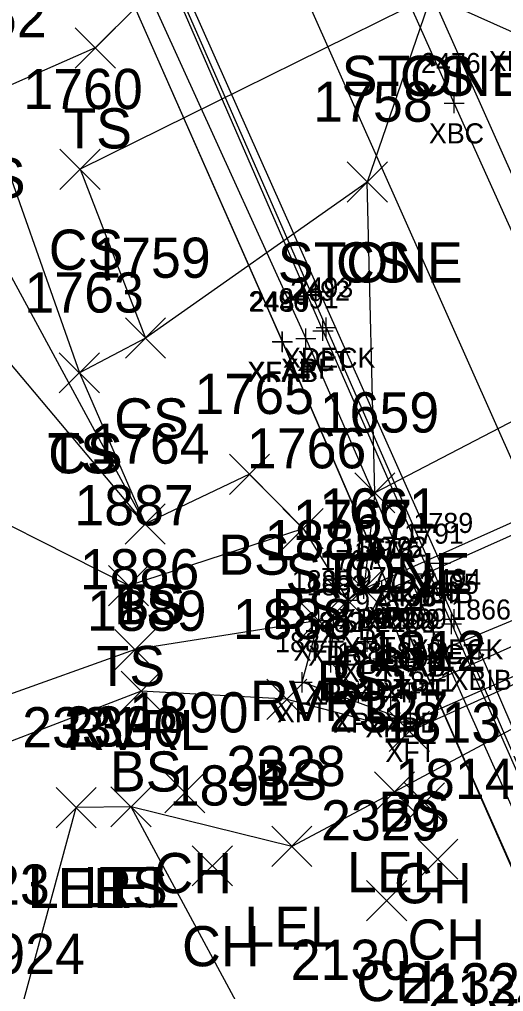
# Model space of a CAD drawing. Extents: x 1504228 to 1506103, y 437717 to 440106.
# Drawn here: x 1505177.43 to 1505201.55, y 438165.51 to 438213.89 of the extents above; entities that cross this region are included whole.
import ezdxf

# ---------------------------------------------------------------- set-up
doc = ezdxf.new("R2010")
doc.units = 0
for name, color, linetype in [('B_A', 7, 'Continuous'), ('B_I', 7, 'Continuous'), ('B_TIC', 7, 'Continuous'), ('BB', 7, 'Continuous'), ('BDC', 7, 'Continuous'), ('BELB', 7, 'Continuous'), ('BF', 7, 'Continuous'), ('BFT', 7, 'Continuous'), ('BR', 7, 'Continuous'), ('BSUBM', 7, 'Continuous'), ('L_A', 7, 'Continuous'), ('L_I', 7, 'Continuous'), ('L_TIC', 7, 'Continuous'), ('LARO', 7, 'Continuous'), ('LASF', 7, 'Continuous'), ('LAWE', 7, 'Continuous'), ('LELB', 7, 'Continuous')]:
    doc.layers.add(name, color=color, linetype=linetype)

msp = doc.modelspace()

# ---------------------------------------------------------------- linework, layer by layer
at = {"layer": 'B_TIC'}
for p, q in [((1505199.096, 438209.718), (1505199.172, 438209.718)), ((1505192.559, 438198.391), (1505192.634, 438198.391)), ((1505192.72, 438198.549), (1505192.795, 438198.549)), ((1505190.521, 438197.862), (1505190.596, 438197.862)), ((1505190.544, 438197.836), (1505190.62, 438197.836)), ((1505191.703, 438198.009), (1505191.779, 438198.009)), ((1505198.413, 438186.83), (1505198.489, 438186.83)), ((1505197.658, 438186.296), (1505197.734, 438186.296)), ((1505196.095, 438185.646), (1505196.171, 438185.646)), ((1505194.585, 438185.548), (1505194.661, 438185.548)), ((1505195.488, 438185.416), (1505195.563, 438185.416)), ((1505195.886, 438185.587), (1505195.962, 438185.587)), ((1505193.792, 438184.98), (1505193.867, 438184.98)), ((1505192.345, 438183.974), (1505192.421, 438183.974)), ((1505193.085, 438183.722), (1505193.16, 438183.722)), ((1505193.085, 438183.722), (1505193.16, 438183.722)), ((1505194.849, 438184.144), (1505194.925, 438184.144)), ((1505198.964, 438183.8), (1505199.039, 438183.8)), ((1505199.093, 438184.038), (1505199.168, 438184.038)), ((1505196.854, 438183.23), (1505196.929, 438183.23)), ((1505198.06, 438183.407), (1505198.135, 438183.407)), ((1505194.765, 438182.92), (1505194.84, 438182.92)), ((1505196.881, 438183.176), (1505196.957, 438183.176)), ((1505200.343, 438182.519), (1505200.419, 438182.519)), ((1505192.955, 438181.893), (1505193.03, 438181.893)), ((1505195.545, 438182.063), (1505195.621, 438182.063)), ((1505196.815, 438181.895), (1505196.89, 438181.895)), ((1505197.342, 438182.037), (1505197.418, 438182.037)), ((1505197.379, 438182.065), (1505197.455, 438182.065)), ((1505191.52, 438180.897), (1505191.595, 438180.897)), ((1505194.333, 438180.389), (1505194.409, 438180.389)), ((1505196.874, 438180.394), (1505196.949, 438180.394)), ((1505195.932, 438180.154), (1505196.008, 438180.154)), ((1505196.924, 438178.938), (1505196.999, 438178.938))]:
    msp.add_line(p, q, dxfattribs=at)
for points in [[(1505199.093, 438209.218), (1505199.093, 438210.218)], [(1505198.593, 438209.718), (1505199.593, 438209.718)], [(1505192.555, 438197.891), (1505192.555, 438198.891)], [(1505192.716, 438198.049), (1505192.716, 438199.049)], [(1505190.518, 438197.362), (1505190.518, 438198.362)], [(1505190.541, 438197.336), (1505190.541, 438198.336)], [(1505191.7, 438197.509), (1505191.7, 438198.509)], [(1505192.055, 438198.391), (1505193.055, 438198.391)], [(1505192.216, 438198.549), (1505193.216, 438198.549)], [(1505190.018, 438197.862), (1505191.018, 438197.862)], [(1505190.041, 438197.836), (1505191.041, 438197.836)], [(1505191.2, 438198.009), (1505192.2, 438198.009)], [(1505198.41, 438186.33), (1505198.41, 438187.33)], [(1505197.655, 438185.796), (1505197.655, 438186.796)], [(1505197.91, 438186.83), (1505198.91, 438186.83)], [(1505196.092, 438185.146), (1505196.092, 438186.146)], [(1505197.155, 438186.296), (1505198.155, 438186.296)], [(1505194.582, 438185.048), (1505194.582, 438186.048)], [(1505195.484, 438184.916), (1505195.484, 438185.916)], [(1505195.592, 438185.646), (1505196.592, 438185.646)], [(1505195.883, 438185.087), (1505195.883, 438186.087)], [(1505193.788, 438184.48), (1505193.788, 438185.48)], [(1505194.082, 438185.548), (1505195.082, 438185.548)], [(1505194.984, 438185.416), (1505195.984, 438185.416)], [(1505195.383, 438185.587), (1505196.383, 438185.587)], [(1505193.288, 438184.98), (1505194.288, 438184.98)], [(1505192.342, 438183.474), (1505192.342, 438184.474)], [(1505193.081, 438183.222), (1505193.081, 438184.222)], [(1505193.081, 438183.222), (1505193.081, 438184.222)], [(1505194.846, 438183.644), (1505194.846, 438184.644)], [(1505198.96, 438183.3), (1505198.96, 438184.3)], [(1505199.089, 438183.538), (1505199.089, 438184.538)], [(1505191.842, 438183.974), (1505192.842, 438183.974)], [(1505192.581, 438183.722), (1505193.581, 438183.722)], [(1505192.581, 438183.722), (1505193.581, 438183.722)], [(1505194.346, 438184.144), (1505195.346, 438184.144)], [(1505196.85, 438182.73), (1505196.85, 438183.73)], [(1505198.057, 438182.907), (1505198.057, 438183.907)], [(1505198.46, 438183.8), (1505199.46, 438183.8)], [(1505198.589, 438184.038), (1505199.589, 438184.038)], [(1505194.761, 438182.42), (1505194.761, 438183.42)], [(1505196.35, 438183.23), (1505197.35, 438183.23)], [(1505196.878, 438182.676), (1505196.878, 438183.676)], [(1505197.557, 438183.407), (1505198.557, 438183.407)], [(1505194.261, 438182.92), (1505195.261, 438182.92)], [(1505196.378, 438183.176), (1505197.378, 438183.176)], [(1505200.34, 438182.019), (1505200.34, 438183.019)], [(1505192.951, 438181.393), (1505192.951, 438182.393)], [(1505195.542, 438181.563), (1505195.542, 438182.563)], [(1505196.811, 438181.395), (1505196.811, 438182.395)], [(1505197.339, 438181.537), (1505197.339, 438182.537)], [(1505197.376, 438181.565), (1505197.376, 438182.565)], [(1505199.84, 438182.519), (1505200.84, 438182.519)], [(1505192.451, 438181.893), (1505193.451, 438181.893)], [(1505195.042, 438182.063), (1505196.042, 438182.063)], [(1505196.311, 438181.895), (1505197.311, 438181.895)], [(1505196.839, 438182.037), (1505197.839, 438182.037)], [(1505196.876, 438182.065), (1505197.876, 438182.065)], [(1505191.516, 438180.397), (1505191.516, 438181.397)], [(1505191.016, 438180.897), (1505192.016, 438180.897)], [(1505194.33, 438179.889), (1505194.33, 438180.889)], [(1505196.87, 438179.894), (1505196.87, 438180.894)], [(1505193.83, 438180.389), (1505194.83, 438180.389)], [(1505195.929, 438179.654), (1505195.929, 438180.654)], [(1505196.37, 438180.394), (1505197.37, 438180.394)], [(1505195.429, 438180.154), (1505196.429, 438180.154)], [(1505196.92, 438178.438), (1505196.92, 438179.438)], [(1505196.42, 438178.938), (1505197.42, 438178.938)]]:
    msp.add_lwpolyline(points, dxfattribs=at)
at = {"layer": 'BB'}
for points in [[(1505190.469, 438231.914), (1505208.63, 438191.227)], [(1505185.111, 438229.788), (1505203.304, 438188.941)], [(1505180.341, 438227.325), (1505198.41, 438186.83)], [(1505218.208, 438141.011), (1505200.34, 438182.519)]]:
    msp.add_lwpolyline(points, dxfattribs=at)
at = {"layer": 'BDC'}
msp.add_lwpolyline([(1505177.99, 438228.719), (1505178.876, 438228.45), (1505180.438, 438226.195), (1505192.555, 438198.391), (1505198.96, 438183.8), (1505208.446, 438162.36), (1505217.081, 438142.744), (1505218.046, 438139.452)], dxfattribs=at)
at = {"layer": 'BELB'}
for points in [[(1505199.093, 438209.718), (1505189.093, 438232.07)], [(1505179.043, 438228.597), (1505180.553, 438226.219), (1505192.716, 438198.549), (1505199.089, 438184.038), (1505208.574, 438162.333), (1505217.312, 438142.723), (1505218.32, 438139.52)], [(1505227.121, 438143.057), (1505216.699, 438169.498), (1505208.631, 438188.54), (1505199.093, 438209.718)]]:
    msp.add_lwpolyline(points, dxfattribs=at)
at = {"layer": 'BF'}
for points in [[(1505177.99, 438228.719), (1505179.189, 438225.504), (1505178.468, 438225.175), (1505190.518, 438197.862), (1505196.85, 438183.23), (1505206.498, 438161.372), (1505215.121, 438141.85), (1505216.234, 438142.341), (1505217.418, 438139.282), (1505218.046, 438139.452)], [(1505178.471, 438225.17), (1505190.541, 438197.836), (1505196.878, 438183.176), (1505206.558, 438161.349), (1505215.066, 438141.897)]]:
    msp.add_lwpolyline(points, dxfattribs=at)
at = {"layer": 'BFT'}
msp.add_lwpolyline([(1505252.998, 438208.079), (1505252.263, 438206.145), (1505250.763, 438202.931), (1505232.133, 438194.68), (1505231.606, 438194.296), (1505223.29, 438190.638), (1505216.076, 438187.39), (1505206.938, 438183.343), (1505196.92, 438178.938), (1505191.516, 438180.897), (1505192.342, 438183.974)], dxfattribs=at)
at = {"layer": 'BR'}
msp.add_lwpolyline([(1505179.189, 438225.504), (1505191.7, 438198.009), (1505198.057, 438183.407), (1505207.736, 438161.768), (1505216.234, 438142.341)], dxfattribs=at)
at = {"layer": 'BSUBM'}
for points in [[(1505251.673, 438208.67), (1505250, 438209.507), (1505248.317, 438209.426), (1505235.511, 438203.792), (1505229.335, 438201.006), (1505222.013, 438197.676), (1505217.996, 438195.981), (1505203.564, 438189.562), (1505194.582, 438185.548), (1505193.788, 438184.98), (1505193.081, 438183.722)], [(1505251.673, 438208.67), (1505252.263, 438206.145), (1505250.569, 438204.342), (1505231.52, 438195.759), (1505231.146, 438195.559), (1505222.778, 438191.886), (1505216.199, 438188.925), (1505206.374, 438184.654), (1505196.87, 438180.394), (1505195.929, 438180.154), (1505194.33, 438180.389), (1505192.951, 438181.893), (1505193.081, 438183.722)], [(1505209.571, 438191.61), (1505197.655, 438186.296), (1505196.092, 438185.646), (1505195.883, 438185.587), (1505195.484, 438185.416), (1505194.846, 438184.144), (1505194.761, 438182.92), (1505195.542, 438182.063), (1505196.811, 438181.895), (1505197.339, 438182.037), (1505197.376, 438182.065), (1505223.277, 438192.822)], [(1505196.811, 438181.895), (1505195.484, 438185.416)], [(1505195.883, 438185.587), (1505197.339, 438182.037)]]:
    msp.add_lwpolyline(points, dxfattribs=at)
at = {"layer": 'L_TIC'}
for points in [[(1505180.214, 438211.467), (1505182.214, 438213.467)], [(1505182.214, 438211.467), (1505180.214, 438213.467)], [(1505180.214, 438211.467), (1505182.214, 438213.467)], [(1505182.214, 438211.467), (1505180.214, 438213.467)], [(1505179.455, 438205.428), (1505181.455, 438207.428)], [(1505181.455, 438205.428), (1505179.455, 438207.428)], [(1505193.762, 438204.795), (1505195.762, 438206.795)], [(1505195.762, 438204.795), (1505193.762, 438206.795)], [(1505193.762, 438204.795), (1505195.762, 438206.795)], [(1505195.762, 438204.795), (1505193.762, 438206.795)], [(1505193.762, 438204.795), (1505195.762, 438206.795)], [(1505195.762, 438204.795), (1505193.762, 438206.795)], [(1505182.712, 438197.029), (1505184.712, 438199.029)], [(1505184.712, 438197.029), (1505182.712, 438199.029)], [(1505179.422, 438195.297), (1505181.422, 438197.297)], [(1505181.422, 438195.297), (1505179.422, 438197.297)], [(1505179.422, 438195.297), (1505181.422, 438197.297)], [(1505181.422, 438195.297), (1505179.422, 438197.297)], [(1505187.896, 438190.25), (1505189.896, 438192.25)], [(1505189.896, 438190.25), (1505187.896, 438192.25)], [(1505194.139, 438189.329), (1505196.139, 438191.329)], [(1505196.139, 438189.329), (1505194.139, 438191.329)], [(1505194.139, 438189.329), (1505196.139, 438191.329)], [(1505196.139, 438189.329), (1505194.139, 438191.329)], [(1505182.694, 438187.776), (1505184.694, 438189.776)], [(1505184.694, 438187.776), (1505182.694, 438189.776)], [(1505182.694, 438187.776), (1505184.694, 438189.776)], [(1505184.694, 438187.776), (1505182.694, 438189.776)], [(1505190.559, 438187.545), (1505192.559, 438189.545)], [(1505192.559, 438187.545), (1505190.559, 438189.545)], [(1505181.865, 438184.709), (1505183.865, 438186.709)], [(1505183.865, 438184.709), (1505181.865, 438186.709)], [(1505193.582, 438184.548), (1505195.582, 438186.548)], [(1505195.582, 438184.548), (1505193.582, 438186.548)], [(1505192.788, 438183.98), (1505194.788, 438185.98)], [(1505194.788, 438183.98), (1505192.788, 438185.98)], [(1505191.342, 438182.974), (1505193.342, 438184.974)], [(1505193.342, 438182.974), (1505191.342, 438184.974)], [(1505182.193, 438181.526), (1505184.193, 438183.526)], [(1505184.193, 438181.526), (1505182.193, 438183.526)], [(1505182.502, 438179.459), (1505184.502, 438181.459)], [(1505184.502, 438179.459), (1505182.502, 438181.459)], [(1505189.754, 438179.051), (1505191.754, 438181.051)], [(1505191.754, 438179.051), (1505189.754, 438181.051)], [(1505195.859, 438177.456), (1505197.859, 438179.456)], [(1505197.859, 438177.456), (1505195.859, 438179.456)], [(1505195.112, 438174.447), (1505197.112, 438176.447)], [(1505197.112, 438174.447), (1505195.112, 438176.447)], [(1505184.674, 438174.402), (1505186.674, 438176.402)], [(1505186.674, 438174.402), (1505184.674, 438176.402)], [(1505179.265, 438173.662), (1505181.265, 438175.662)], [(1505181.265, 438173.662), (1505179.265, 438175.662)], [(1505179.265, 438173.662), (1505181.265, 438175.662)], [(1505181.265, 438173.662), (1505179.265, 438175.662)], [(1505181.993, 438173.698), (1505183.993, 438175.698)], [(1505183.993, 438173.698), (1505181.993, 438175.698)], [(1505181.993, 438173.698), (1505183.993, 438175.698)], [(1505183.993, 438173.698), (1505181.993, 438175.698)], [(1505196.607, 438173.896), (1505198.607, 438175.896)], [(1505198.607, 438173.896), (1505196.607, 438175.896)], [(1505189.999, 438171.732), (1505191.999, 438173.732)], [(1505191.999, 438171.732), (1505189.999, 438173.732)], [(1505197.274, 438171.094), (1505199.274, 438173.094)], [(1505199.274, 438171.094), (1505197.274, 438173.094)], [(1505186.045, 438170.764), (1505188.045, 438172.764)], [(1505188.045, 438170.764), (1505186.045, 438172.764)], [(1505194.729, 438169.028), (1505196.729, 438171.028)], [(1505196.729, 438169.028), (1505194.729, 438171.028)]]:
    msp.add_lwpolyline(points, dxfattribs=at)
at = {"layer": 'LARO'}
for points in [[(1505257.789, 438202.997), (1505250.211, 438200.467), (1505241.258, 438195.88), (1505230.318, 438190.813), (1505221.077, 438187.488), (1505211.673, 438183.738), (1505205.073, 438180.218), (1505196.112, 438175.447), (1505190.999, 438172.732), (1505182.993, 438174.698), (1505180.265, 438174.662)], [(1505168.002, 438119.282), (1505172.649, 438139.038), (1505173.824, 438143.837), (1505173.651, 438150.434), (1505180.265, 438174.662)]]:
    msp.add_lwpolyline(points, dxfattribs=at)
at = {"layer": 'LASF'}
for points in [[(1505231.536, 438240.553), (1505235.748, 438236.802), (1505232.624, 438230.462), (1505239.591, 438224.256), (1505247.096, 438215.294), (1505232.375, 438208.772), (1505219.716, 438203.952), (1505216.343, 438201.336), (1505195.139, 438190.329), (1505194.762, 438205.795)], [(1505200.461, 438236.399), (1505203.313, 438230.133), (1505201.377, 438228.793), (1505197.941, 438215.08), (1505194.762, 438205.795)]]:
    msp.add_lwpolyline(points, dxfattribs=at)
at = {"layer": 'LAWE'}
msp.add_lwpolyline([(1505192.342, 438183.974), (1505183.193, 438182.526), (1505169.265, 438177.558), (1505163.184, 438169.103), (1505153.153, 438165.832), (1505148.603, 438168.433), (1505142.16, 438169.739), (1505121.865, 438175.913), (1505102.347, 438176.333), (1505081.308, 438180.613), (1505065.507, 438182.877)], dxfattribs=at)
at = {"layer": 'LELB'}
for points in [[(1505345.996, 438335.597), (1505333.305, 438314.456), (1505321.287, 438297.225), (1505312.638, 438280.068), (1505305.643, 438263.855), (1505289.682, 438249.994), (1505275.731, 438243.689), (1505265.066, 438236.954), (1505253.57, 438228.442), (1505232.624, 438230.462), (1505221.792, 438235.116), (1505209.888, 438231.849), (1505203.313, 438230.133), (1505201.377, 438228.793), (1505195.715, 438225.539), (1505189.868, 438221.089), (1505181.214, 438212.467), (1505175.582, 438209.995), (1505180.422, 438196.297), (1505183.694, 438188.776), (1505173.648, 438207.305)], [(1505365.146, 438316.099), (1505353.966, 438296.236), (1505341.915, 438275.153), (1505332.016, 438262.134), (1505323.954, 438252.628), (1505313.563, 438242.629), (1505305.646, 438236.558), (1505295.746, 438229.78), (1505286.64, 438224.685), (1505273.677, 438216.738), (1505262.485, 438213.279), (1505253.251, 438208.207), (1505250.962, 438202.759), (1505231.919, 438194.06), (1505223.449, 438190.476), (1505215.829, 438187.003), (1505207.689, 438183.331), (1505196.859, 438178.456)], [(1505270.798, 438231.377), (1505256.305, 438221.751), (1505239.591, 438224.256), (1505218.796, 438213.879), (1505204.191, 438212.28), (1505197.941, 438215.08), (1505180.455, 438206.428)], [(1505183.694, 438188.776), (1505168.807, 438206.471)], [(1505180.455, 438206.428), (1505183.712, 438198.029)], [(1505194.762, 438205.795), (1505183.712, 438198.029), (1505180.422, 438196.297)], [(1505188.896, 438191.25), (1505183.694, 438188.776)], [(1505188.896, 438191.25), (1505191.559, 438188.545), (1505193.788, 438184.98)], [(1505182.865, 438185.709), (1505172.67, 438190.86), (1505161.167, 438179.869)], [(1505195.139, 438190.329), (1505194.582, 438185.548)], [(1505182.865, 438185.709), (1505191.559, 438188.545)], [(1505190.754, 438180.051), (1505183.502, 438180.459), (1505172.002, 438176.044), (1505165.088, 438168.018), (1505153.497, 438163.2), (1505142.827, 438168.143), (1505121.603, 438174.613), (1505101.25, 438173.927), (1505080.769, 438178.505), (1505064.451, 438180.678)], [(1505190.754, 438180.051), (1505196.859, 438178.456)], [(1505177.453, 438144.004), (1505189.028, 438155.358), (1505190.722, 438160.403), (1505182.993, 438174.698)]]:
    msp.add_lwpolyline(points, dxfattribs=at)

# ---------------------------------------------------------------- texts
at = {"layer": 'B_A'}
for s, p in [('XBC', (1505200.811, 438211.317)), ('XBC', (1505197.829, 438207.718)), ('XDECK', (1505190.559, 438196.549)), ('XCT', (1505191.276, 438196.391)), ('XFAT', (1505188.773, 438195.862)), ('XFAB', (1505188.813, 438195.836)), ('XRF', (1505190.46, 438196.009)), ('XBIB', (1505196.981, 438184.83)), ('XPT', (1505196.375, 438184.296)), ('XPB', (1505193.318, 438183.548)), ('XPT', (1505194.205, 438183.416)), ('XPT', (1505194.603, 438183.587)), ('XPT', (1505194.812, 438183.646)), ('XPB', (1505192.525, 438182.98)), ('XFT', (1505191.086, 438181.974)), ('XPB', (1505191.817, 438181.722)), ('XPB', (1505191.817, 438181.722)), ('XPT', (1505193.566, 438182.144)), ('XDECK', (1505196.932, 438182.038)), ('XCT', (1505197.681, 438181.8)), ('XRF', (1505196.816, 438181.407)), ('XPT', (1505193.482, 438180.92)), ('XFAT', (1505195.106, 438181.23)), ('XFAB', (1505195.15, 438181.176)), ('XBIB', (1505198.911, 438180.519)), ('XPB', (1505191.687, 438179.893)), ('XPT', (1505194.262, 438180.063)), ('XPT', (1505195.532, 438179.895)), ('XPT', (1505196.059, 438180.037)), ('XPT', (1505196.096, 438180.065)), ('XFT', (1505190.26, 438178.897)), ('XPB', (1505193.066, 438178.389)), ('XPB', (1505195.607, 438178.394)), ('XPB', (1505194.665, 438178.154)), ('XFT', (1505195.664, 438176.938))]:
    msp.add_text(s, height=1, dxfattribs=at).set_placement(p)
at = {"layer": 'B_I'}
for s, p in [('2476', (1505197.435, 438211.218)), ('2492', (1505190.925, 438199.891)), ('2493', (1505191.086, 438200.049)), ('2490', (1505188.844, 438199.362)), ('2489', (1505188.907, 438199.336)), ('2491', (1505190.353, 438199.509)), ('1789', (1505197.06, 438188.33)), ('1791', (1505196.592, 438187.796)), ('1661', (1505193.472, 438187.048)), ('1975', (1505194.536, 438187.087)), ('1792', (1505194.745, 438187.146)), ('1976', (1505194.11, 438186.916)), ('1767', (1505192.418, 438186.48)), ('1977', (1505193.5, 438185.644)), ('1885', (1505190.995, 438185.474)), ('1883', (1505191.735, 438185.222)), ('1883', (1505191.735, 438185.222)), ('2495', (1505197.33, 438185.3)), ('2494', (1505197.459, 438185.538)), ('2497', (1505195.22, 438184.73)), ('2498', (1505195.248, 438184.676)), ('2496', (1505196.399, 438184.907)), ('1978', (1505193.415, 438184.42)), ('1866', (1505198.942, 438184.019)), ('1882', (1505191.605, 438183.393)), ('1979', (1505194.192, 438183.563)), ('2298', (1505195.182, 438183.395)), ('2299', (1505195.742, 438183.565)), ('999', (1505196.154, 438183.537)), ('1884', (1505190.17, 438182.397)), ('1881', (1505193.267, 438181.889)), ('1809', (1505195.481, 438181.894)), ('1810', (1505194.822, 438181.654)), ('1811', (1505196.141, 438180.438))]:
    msp.add_text(s, height=1, dxfattribs=at).set_placement(p)
at = {"layer": 'L_A'}
for s, p in [('STONE', (1505193.484, 438210.08)), ('CS', (1505196.382, 438210.08)), ('TS', (1505179.623, 438207.467)), ('TS', (1505179.623, 438207.467)), ('CS', (1505174.023, 438204.995)), ('CS', (1505178.896, 438201.428)), ('STONE', (1505190.305, 438200.795)), ('STONE', (1505190.305, 438200.795)), ('CS', (1505193.203, 438200.795)), ('CS', (1505182.153, 438193.029)), ('TS', (1505178.832, 438191.297)), ('CS', (1505178.863, 438191.297)), ('BS', (1505187.337, 438186.25)), ('STONE', (1505190.682, 438185.329)), ('CS', (1505193.58, 438185.329)), ('TS', (1505182.104, 438183.776)), ('BS', (1505182.135, 438183.776)), ('BS', (1505190, 438183.545)), ('TS', (1505181.274, 438180.709)), ('CS', (1505193.023, 438180.548)), ('BS', (1505192.229, 438179.98)), ('RVRL', (1505188.909, 438178.974)), ('RVRL', (1505179.76, 438177.526)), ('BS', (1505181.943, 438175.459)), ('BS', (1505189.195, 438175.051)), ('BS', (1505195.3, 438173.456)), ('CH', (1505184.162, 438170.402)), ('LEL', (1505193.75, 438170.447)), ('LER', (1505177.848, 438169.662)), ('LEL', (1505177.903, 438169.662)), ('LEL', (1505180.631, 438169.698)), ('TS', (1505181.403, 438169.698)), ('CH', (1505196.095, 438169.896)), ('LEL', (1505188.637, 438167.732)), ('CH', (1505185.534, 438166.764)), ('CH', (1505196.762, 438167.094)), ('CH', (1505194.217, 438165.028))]:
    msp.add_text(s, height=2, dxfattribs=at).set_placement(p)
at = {"layer": 'L_I'}
for s, p in [('1762', (1505172.842, 438212.995)), ('1762', (1505172.842, 438212.995)), ('1760', (1505177.628, 438209.428)), ('1758', (1505192.069, 438208.795)), ('1758', (1505192.069, 438208.795)), ('1758', (1505192.069, 438208.795)), ('1759', (1505181.012, 438201.029)), ('1763', (1505177.682, 438199.297)), ('1763', (1505177.682, 438199.297)), ('1765', (1505186.156, 438194.25)), ('1659', (1505192.391, 438193.329)), ('1659', (1505192.391, 438193.329)), ('1764', (1505180.954, 438191.776)), ('1764', (1505180.954, 438191.776)), ('1766', (1505188.764, 438191.545)), ('1887', (1505180.172, 438188.709)), ('1661', (1505192.361, 438188.548)), ('1767', (1505191.048, 438187.98)), ('1885', (1505189.649, 438186.974)), ('1886', (1505180.445, 438185.526)), ('1889', (1505180.801, 438183.459)), ('1888', (1505188.061, 438183.051)), ('1812', (1505194.733, 438181.456)), ('1890', (1505182.895, 438178.402)), ('2327', (1505192.852, 438178.447)), ('1813', (1505195.481, 438177.896)), ('2331', (1505177.572, 438177.662)), ('2331', (1505177.572, 438177.662)), ('2330', (1505179.647, 438177.698)), ('2330', (1505179.647, 438177.698)), ('2328', (1505187.739, 438175.732)), ('1814', (1505196.148, 438175.094)), ('1891', (1505184.919, 438174.764)), ('2329', (1505192.461, 438173.028)), ('1923', (1505172.998, 438169.832)), ('1924', (1505174.743, 438166.385)), ('2130', (1505190.945, 438166.089)), ('2130', (1505190.945, 438166.089)), ('2132', (1505196.421, 438164.918)), ('2134', (1505197.736, 438164.515))]:
    msp.add_text(s, height=2, dxfattribs=at).set_placement(p)

doc.saveas('drawing.dxf')
